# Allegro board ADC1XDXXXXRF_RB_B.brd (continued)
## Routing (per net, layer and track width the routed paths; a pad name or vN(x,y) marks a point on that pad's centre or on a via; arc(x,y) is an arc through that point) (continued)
FMC_DI-5: length 142.1
  TOP w0.102: v1(113.71,92.75) 114.2,93.25 U5.M1
  SIG2 w0.102: v1(113.71,92.75) 113.71,93.02 113.59,93.14 104.16,93.14 98.91,98.4 61.64,98.4 61.42,98.62 61.42,99.64 61.32,99.75 61.11,99.75 61.01,99.64 61.01,98.62 60.79,98.4 60.42,98.4 60.2,98.62 60.2,99.64 60.1,99.75 59.89,99.75 59.79,99.64 59.79,98.62 59.57,98.4 59.2,98.4 58.98,98.62 58.98,99.64 58.88,99.75 58.67,99.75 58.57,99.64 58.57,98.62 58.35,98.4 57.98,98.4 57.76,98.62 57.76,99.67 57.66,99.77 57.45,99.77 57.35,99.67 57.35,98.62 57.13,98.4 56.76,98.4 56.54,98.62 56.54,99.67 56.44,99.77 56.24,99.77 56.13,99.67 56.13,98.62 55.91,98.4 55.54,98.4 55.32,98.62 55.32,99.67 55.22,99.77 55.02,99.77 54.91,99.67 54.91,98.62 54.69,98.4 54.32,98.4 54.1,98.62 54.1,99.67 54,99.77 53.8,99.77 53.7,99.67 53.7,98.62 53.48,98.4 53.1,98.4 52.88,98.62 52.88,99.67 52.78,99.77 52.58,99.77 52.48,99.67 52.48,98.62 52.26,98.4 51.88,98.4 51.66,98.62 51.66,99.67 51.56,99.77 51.36,99.77 51.26,99.67 51.26,98.62 51.04,98.4 50.66,98.4 50.44,98.62 50.44,99.67 50.34,99.77 50.14,99.77 50.04,99.67 50.04,98.62 49.82,98.4 49.45,98.4 49.23,98.62 49.23,99.67 49.12,99.77 48.92,99.77 48.82,99.67 48.82,98.62 48.6,98.4 48.23,98.4 48.01,98.62 48.01,99.67 47.9,99.77 47.7,99.77 47.6,99.67 47.6,98.62 47.38,98.4 47.01,98.4 46.79,98.62 46.79,99.67 46.69,99.77 46.48,99.77 46.38,99.67 46.38,98.62 46.16,98.4 10.28,98.4 9.99,98.68 9.99,99.63 10.24,99.87 11.96,99.87 12.06,99.97 v3(12.06,100.41)
  BOTTOM w0.102: FMC.D24 v3(12.06,100.41)
FMC_DI-6: length 142.1
  TOP w0.102: U5.L6 119.2,94.24 v1(118.7,93.75)
  SIG3 w0.102: v3(80.7,92.79) 80.7,93.12 80.73,93.15 116.52,93.15 117.52,94.15 118.48,94.15 118.7,93.92 v1(118.7,93.75)
  BOTTOM w0.102: v3(80.7,92.79) 80.29,93.19 80.29,103.38 72.98,110.69 55.93,110.69 55.68,110.44 55.68,108.97 55.58,108.86 55.37,108.86 55.27,108.97 55.27,110.44 55.02,110.69 54.61,110.69 54.36,110.44 54.36,108.97 54.26,108.86 54.05,108.86 53.95,108.97 53.95,110.44 53.7,110.69 53.29,110.69 53.04,110.44 53.04,108.97 52.93,108.86 52.73,108.86 52.63,108.97 52.63,110.44 52.38,110.69 51.97,110.69 51.72,110.44 51.72,108.97 51.61,108.86 51.41,108.86 51.31,108.97 51.31,110.44 51.06,110.69 50.65,110.69 50.39,110.44 50.39,108.97 50.29,108.86 50.09,108.86 49.99,108.97 49.99,110.44 49.74,110.69 47.75,110.69 46.66,109.6 46.66,104.52 45.21,103.07 17.53,103.07 17.3,103.3 17.3,105.33 FMC.H29
FMC_DI-7: length 142.2
  TOP w0.102: v1(118.72,94.74) U5.K6
  SIG2 w0.102: v1(118.72,94.74) 118.99,94.74 119.15,94.9 119.15,95.15 118.97,95.33 118.57,95.33 118.32,95.57 118.32,96.01 117.99,96.34 104.5,96.34 97.16,103.68 93.42,103.68 93.32,103.78 93.32,104.02 93.1,104.24 92.73,104.24 92.51,104.02 92.51,103.78 92.41,103.68 92.2,103.68 92.1,103.78 92.1,104.02 91.88,104.24 91.51,104.24 91.29,104.02 91.29,103.78 91.19,103.68 90.98,103.68 90.88,103.78 90.88,104.02 90.66,104.24 90.29,104.24 90.07,104.02 90.07,103.78 89.97,103.68 89.76,103.68 89.66,103.78 89.66,104.02 89.44,104.24 89.07,104.24 88.85,104.02 88.85,103.78 88.75,103.68 88.54,103.68 88.44,103.78 88.44,104.02 88.22,104.24 87.85,104.24 87.63,104.02 87.63,103.78 87.53,103.68 87.33,103.68 87.22,103.78 87.22,104.05 87,104.27 86.63,104.27 86.41,104.05 86.41,103.78 86.31,103.68 86.11,103.68 86,103.78 86,104.05 85.78,104.27 85.41,104.27 85.19,104.05 85.19,103.78 85.09,103.68 84.89,103.68 84.79,103.78 84.79,104.05 84.56,104.27 84.19,104.27 83.97,104.05 83.97,103.78 83.87,103.68 83.67,103.68 83.57,103.78 83.57,104.05 83.35,104.27 82.97,104.27 82.75,104.05 82.75,103.78 82.65,103.68 82.45,103.68 82.35,103.78 82.35,104.05 82.13,104.27 81.75,104.27 81.53,104.05 81.53,103.78 81.43,103.68 81.23,103.68 81.13,103.78 81.13,104.05 80.91,104.27 80.54,104.27 80.31,104.05 80.31,103.78 80.21,103.68 80.01,103.68 79.91,103.78 79.91,104.05 79.69,104.27 79.32,104.27 79.1,104.05 79.1,103.78 78.99,103.68 78.79,103.68 78.69,103.78 78.69,104.05 78.47,104.27 78.1,104.27 77.88,104.05 77.88,103.78 77.77,103.68 77.57,103.68 77.47,103.78 77.47,104.05 77.25,104.27 76.88,104.27 76.66,104.05 76.66,103.78 76.56,103.68 76.35,103.68 76.25,103.78 76.25,104.05 76.03,104.27 75.66,104.27 75.44,104.05 75.44,103.78 75.34,103.68 75.13,103.68 75.03,103.78 75.03,104.05 74.81,104.27 74.44,104.27 74.22,104.05 74.22,103.78 74.12,103.68 73.91,103.68 73.81,103.78 73.81,104.05 73.59,104.27 73.22,104.27 73,104.05 73,103.78 72.9,103.68 72.69,103.68 72.59,103.78 72.59,104.05 72.37,104.27 72,104.27 71.78,104.05 71.78,103.78 71.68,103.68 71.48,103.68 71.37,103.78 71.37,104.05 71.15,104.27 70.78,104.27 70.56,104.05 70.56,103.78 70.46,103.68 70.26,103.68 70.15,103.78 70.15,104.05 69.93,104.27 69.56,104.27 69.34,104.05 69.34,103.78 69.24,103.68 69.04,103.68 68.94,103.78 68.94,104.05 68.72,104.27 68.34,104.27 68.12,104.05 68.12,103.78 68.02,103.68 67.82,103.68 67.72,103.78 67.72,104.05 67.5,104.27 67.12,104.27 66.9,104.05 66.9,103.78 66.8,103.68 66.6,103.68 66.5,103.78 66.5,104.05 66.28,104.27 65.9,104.27 65.68,104.05 65.68,103.78 65.58,103.68 65.38,103.68 65.28,103.78 65.28,104.05 65.06,104.27 64.69,104.27 64.47,104.05 64.47,103.78 64.36,103.68 64.16,103.68 64.06,103.78 64.06,104.05 63.84,104.27 63.47,104.27 63.25,104.05 63.25,103.78 63.14,103.68 62.94,103.68 62.84,103.78 62.84,104.05 62.62,104.27 62.25,104.27 62.03,104.05 62.03,103.78 61.93,103.68 61.72,103.68 61.62,103.78 61.62,104.05 61.4,104.27 61.03,104.27 60.81,104.05 60.81,103.78 60.71,103.68 60.5,103.68 60.4,103.78 60.4,104.05 60.18,104.27 59.81,104.27 59.59,104.05 59.59,103.78 59.49,103.68 59.28,103.68 59.18,103.78 59.18,104.05 58.96,104.27 58.59,104.27 58.37,104.05 58.37,103.78 58.27,103.68 58.06,103.68 57.96,103.78 57.96,104.05 57.74,104.27 57.37,104.27 57.15,104.05 57.15,103.78 57.05,103.68 56.85,103.68 56.74,103.78 56.74,104.05 56.52,104.27 56.15,104.27 55.93,104.05 55.93,103.78 55.83,103.68 55.63,103.68 55.52,103.78 55.52,104.05 55.3,104.27 54.93,104.27 54.71,104.05 54.71,103.78 54.61,103.68 54.41,103.68 54.31,103.78 54.31,104.05 54.08,104.27 53.71,104.27 53.49,104.05 53.49,103.78 53.39,103.68 53.19,103.68 53.09,103.78 53.09,104.05 52.87,104.27 52.49,104.27 52.27,104.05 52.27,103.78 52.17,103.68 51.97,103.68 51.87,103.78 51.87,104.05 51.65,104.27 51.27,104.27 51.05,104.05 51.05,103.78 50.95,103.68 50.75,103.68 50.65,103.78 50.65,104.05 50.43,104.27 50.06,104.27 49.83,104.05 49.83,103.78 49.73,103.68 49.53,103.68 49.43,103.78 49.43,104.05 49.21,104.27 48.84,104.27 48.62,104.05 48.62,103.78 48.51,103.68 48.31,103.68 48.21,103.78 48.21,104.05 47.99,104.27 47.62,104.27 47.4,104.05 47.4,103.78 47.29,103.68 47.09,103.68 46.99,103.78 46.99,104.05 46.77,104.27 46.4,104.27 46.18,104.05 46.18,103.78 46.08,103.68 15.09,103.68 15.04,103.73 15.04,104.17 15.09,104.22 v3(15.88,104.22)
  BOTTOM w0.102: FMC.G28 v3(15.88,104.22)
FMC_DI-8: length 142.1
  TOP w0.102: v1(116.72,94.74) U5.K4
  SIG2 w0.102: v1(116.72,94.74) 117.23,94.74 117.33,94.84 117.33,95.24 117.23,95.34 104.36,95.34 97.29,102.41 88.54,102.41 88.44,102.51 88.44,102.83 88.22,103.05 87.85,103.05 87.63,102.83 87.63,102.51 87.53,102.41 87.33,102.41 87.22,102.51 87.22,102.83 87,103.05 86.63,103.05 86.41,102.83 86.41,102.51 86.31,102.41 86.11,102.41 86,102.51 86,102.83 85.78,103.05 85.41,103.05 85.19,102.83 85.19,102.51 85.09,102.41 84.89,102.41 84.79,102.51 84.79,102.83 84.56,103.05 84.19,103.05 83.97,102.83 83.97,102.51 83.87,102.41 83.67,102.41 83.57,102.51 83.57,102.8 83.35,103.02 82.97,103.02 82.75,102.8 82.75,102.51 82.65,102.41 82.45,102.41 82.35,102.51 82.35,102.83 82.13,103.05 81.75,103.05 81.53,102.83 81.53,102.51 81.43,102.41 81.23,102.41 81.13,102.51 81.13,102.83 80.91,103.05 80.54,103.05 80.31,102.83 80.31,102.51 80.21,102.41 80.01,102.41 79.91,102.51 79.91,102.8 79.69,103.02 79.32,103.02 79.1,102.8 79.1,102.51 78.99,102.41 78.79,102.41 78.69,102.51 78.69,102.8 78.47,103.02 78.1,103.02 77.88,102.8 77.88,102.51 77.77,102.41 77.57,102.41 77.47,102.51 77.47,102.8 77.25,103.02 76.88,103.02 76.66,102.8 76.66,102.51 76.56,102.41 76.35,102.41 76.25,102.51 76.25,102.8 76.03,103.02 75.66,103.02 75.44,102.8 75.44,102.51 75.34,102.41 75.13,102.41 75.03,102.51 75.03,102.8 74.81,103.02 74.44,103.02 74.22,102.8 74.22,102.51 74.12,102.41 73.91,102.41 73.81,102.51 73.81,102.8 73.59,103.02 73.22,103.02 73,102.8 73,102.51 72.9,102.41 72.69,102.41 72.59,102.51 72.59,102.8 72.37,103.02 72,103.02 71.78,102.8 71.78,102.51 71.68,102.41 71.48,102.41 71.37,102.51 71.37,102.8 71.15,103.02 70.78,103.02 70.56,102.8 70.56,102.51 70.46,102.41 70.26,102.41 70.15,102.51 70.15,102.8 69.93,103.02 69.56,103.02 69.34,102.8 69.34,102.51 69.24,102.41 69.04,102.41 68.94,102.51 68.94,102.8 68.72,103.02 68.34,103.02 68.12,102.8 68.12,102.51 68.02,102.41 67.82,102.41 67.72,102.51 67.72,102.8 67.5,103.02 67.12,103.02 66.9,102.8 66.9,102.51 66.8,102.41 66.6,102.41 66.5,102.51 66.5,102.8 66.28,103.02 65.9,103.02 65.68,102.8 65.68,102.51 65.58,102.41 65.38,102.41 65.28,102.51 65.28,102.8 65.06,103.02 64.69,103.02 64.47,102.8 64.47,102.51 64.36,102.41 64.16,102.41 64.06,102.51 64.06,102.8 63.84,103.02 63.47,103.02 63.25,102.8 63.25,102.51 63.14,102.41 62.94,102.41 62.84,102.51 62.84,102.8 62.62,103.02 62.25,103.02 62.03,102.8 62.03,102.51 61.93,102.41 61.72,102.41 61.62,102.51 61.62,102.8 61.4,103.02 61.03,103.02 60.81,102.8 60.81,102.51 60.71,102.41 60.5,102.41 60.4,102.51 60.4,102.8 60.18,103.02 59.81,103.02 59.59,102.8 59.59,102.51 59.49,102.41 59.28,102.41 59.18,102.51 59.18,102.8 58.96,103.02 58.59,103.02 58.37,102.8 58.37,102.51 58.27,102.41 58.06,102.41 57.96,102.51 57.96,102.8 57.74,103.02 57.37,103.02 57.15,102.8 57.15,102.51 57.05,102.41 56.85,102.41 56.74,102.51 56.74,102.8 56.52,103.02 56.15,103.02 55.93,102.8 55.93,102.51 55.83,102.41 55.63,102.41 55.52,102.51 55.52,102.8 55.3,103.02 54.93,103.02 54.71,102.8 54.71,102.51 54.61,102.41 54.41,102.41 54.31,102.51 54.31,102.8 54.08,103.02 53.71,103.02 53.49,102.8 53.49,102.51 53.39,102.41 53.19,102.41 53.09,102.51 53.09,102.8 52.87,103.02 52.49,103.02 52.27,102.8 52.27,102.51 52.17,102.41 51.97,102.41 51.87,102.51 51.87,102.8 51.65,103.02 51.27,103.02 51.05,102.8 51.05,102.51 50.95,102.41 50.75,102.41 50.65,102.51 50.65,102.8 50.43,103.02 50.06,103.02 49.83,102.8 49.83,102.51 49.73,102.41 49.53,102.41 49.43,102.51 49.43,102.8 49.21,103.02 48.84,103.02 48.62,102.8 48.62,102.51 48.51,102.41 48.31,102.41 48.21,102.51 48.21,102.8 47.99,103.02 47.62,103.02 47.4,102.8 47.4,102.51 47.29,102.41 47.09,102.41 46.99,102.51 46.99,102.8 46.77,103.02 46.4,103.02 46.18,102.8 46.18,102.51 46.08,102.41 11.63,102.41 11.53,102.51 11.53,102.82 11.66,102.95 v3(12.06,102.95)
  BOTTOM w0.102: FMC.D27 v3(12.06,102.95)
FMC_DI-9: length 142.1
  TOP w0.102: v1(116.72,95.75) U5.J4
  SIG1 w0.102: v3(10.79,104.22) 10.79,103.78 10.9,103.68 46.07,103.68 46.17,103.78 46.17,104.05 46.39,104.27 46.76,104.27 46.98,104.05 46.98,103.78 47.09,103.68 47.29,103.68 47.39,103.78 47.39,104.05 47.61,104.27 47.98,104.27 48.2,104.05 48.2,103.78 48.3,103.68 48.51,103.68 48.61,103.78 48.61,104.05 48.83,104.27 49.2,104.27 49.42,104.05 49.42,103.78 49.52,103.68 49.73,103.68 49.83,103.78 49.83,104.05 50.05,104.27 50.42,104.27 50.64,104.05 50.64,103.78 50.74,103.68 50.95,103.68 51.05,103.78 51.05,104.05 51.27,104.27 51.64,104.27 51.86,104.05 51.86,103.78 51.96,103.68 52.17,103.68 52.27,103.78 52.27,104.05 52.49,104.27 52.86,104.27 53.08,104.05 53.08,103.78 53.18,103.68 53.38,103.68 53.49,103.78 53.49,104.05 53.71,104.27 54.08,104.27 54.3,104.05 54.3,103.78 54.4,103.68 54.6,103.68 54.71,103.78 54.71,104.05 54.93,104.27 55.3,104.27 55.52,104.05 55.52,103.78 55.62,103.68 55.82,103.68 55.92,103.78 55.92,104.05 56.15,104.27 56.52,104.27 56.74,104.05 56.74,103.78 56.84,103.68 57.04,103.68 57.14,103.78 57.14,104.05 57.36,104.27 57.74,104.27 57.96,104.05 57.96,103.78 58.06,103.68 58.26,103.68 58.36,103.78 58.36,104.05 58.58,104.27 58.96,104.27 59.18,104.05 59.18,103.78 59.28,103.68 59.48,103.68 59.58,103.78 59.58,104.05 59.8,104.27 60.17,104.27 60.4,104.05 60.4,103.78 60.5,103.68 60.7,103.68 60.8,103.78 60.8,104.05 61.02,104.27 61.39,104.27 61.61,104.05 61.61,103.78 61.72,103.68 61.92,103.68 62.02,103.78 62.02,104.05 62.24,104.27 62.61,104.27 62.83,104.05 62.83,103.78 62.94,103.68 63.14,103.68 63.24,103.78 63.24,104.05 63.46,104.27 63.83,104.27 64.05,104.05 64.05,103.78 64.15,103.68 64.36,103.68 64.46,103.78 64.46,104.05 64.68,104.27 65.05,104.27 65.27,104.05 65.27,103.78 65.37,103.68 65.58,103.68 65.68,103.78 65.68,104.05 65.9,104.27 66.27,104.27 66.49,104.05 66.49,103.78 66.59,103.68 66.8,103.68 66.9,103.78 66.9,104.05 67.12,104.27 67.49,104.27 67.71,104.05 67.71,103.78 67.81,103.68 68.02,103.68 68.12,103.78 68.12,104.05 68.34,104.27 68.71,104.27 68.93,104.05 68.93,103.78 69.03,103.68 69.23,103.68 69.34,103.78 69.34,104.05 69.56,104.27 69.93,104.27 70.15,104.05 70.15,103.78 70.25,103.68 70.45,103.68 70.56,103.78 70.56,104.05 70.78,104.27 71.15,104.27 71.37,104.05 71.37,103.78 71.47,103.68 71.67,103.68 71.77,103.78 71.77,104.05 72,104.27 72.37,104.27 72.59,104.05 72.59,103.78 72.69,103.68 72.89,103.68 72.99,103.78 72.99,104.05 73.21,104.27 73.59,104.27 73.81,104.05 73.81,103.78 73.91,103.68 74.11,103.68 74.21,103.78 74.21,104.05 74.43,104.27 74.81,104.27 75.03,104.05 75.03,103.78 75.13,103.68 75.33,103.68 75.43,103.78 75.43,104.05 75.65,104.27 76.02,104.27 76.24,104.05 76.24,103.78 76.35,103.68 76.55,103.68 76.65,103.78 76.65,104.05 76.87,104.27 77.24,104.27 77.46,104.05 77.46,103.78 77.57,103.68 77.77,103.68 77.87,103.78 77.87,104.05 78.09,104.27 78.46,104.27 78.68,104.05 78.68,103.78 78.78,103.68 78.99,103.68 79.09,103.78 79.09,104.05 79.31,104.27 79.68,104.27 79.9,104.05 79.9,103.78 80,103.68 80.21,103.68 80.31,103.78 80.31,104.05 80.53,104.27 80.9,104.27 81.12,104.05 81.12,103.78 81.22,103.68 81.43,103.68 81.53,103.78 81.53,104.05 81.75,104.27 82.12,104.27 82.34,104.05 82.34,103.78 82.44,103.68 82.65,103.68 82.75,103.78 82.75,104.02 82.97,104.24 83.34,104.24 83.56,104.02 83.56,103.78 83.66,103.68 83.86,103.68 83.97,103.78 83.97,104.02 84.19,104.24 84.56,104.24 84.78,104.02 84.78,103.78 84.88,103.68 85.08,103.68 85.19,103.78 85.19,104.02 85.41,104.24 85.78,104.24 86,104.02 86,103.78 86.1,103.68 86.3,103.68 86.4,103.78 86.4,104.02 86.63,104.24 87,104.24 87.22,104.02 87.22,103.78 87.32,103.68 87.52,103.68 87.62,103.78 87.62,104.02 87.84,104.24 88.22,104.24 88.44,104.02 88.44,103.78 88.54,103.68 98.43,103.68 108.77,93.35 115.98,93.35 117.12,94.49 117.12,95.5 116.88,95.75 v1(116.72,95.75)
  BOTTOM w0.102: FMC.C27 v3(10.79,104.22)
FMC_DI-10: length 142
  TOP w0.102: U5.K1 113.85,94.87 113.44,94.87 112.94,95.37 111.98,95.37 v1(111.61,95.75)
  SIG1 w0.102: v3(15.88,109.3) 16.41,108.76 16.82,108.76 18.09,107.49 47.26,107.49 47.37,107.59 47.37,108.97 47.59,109.19 47.96,109.19 48.18,108.97 48.18,107.59 48.28,107.49 48.48,107.49 48.58,107.59 48.58,108.97 48.8,109.19 49.18,109.19 49.4,108.97 49.4,107.59 49.5,107.49 49.7,107.49 49.8,107.59 49.8,108.97 50.02,109.19 50.4,109.19 50.62,108.97 50.62,107.59 50.72,107.49 50.92,107.49 51.02,107.59 51.02,108.97 51.24,109.19 51.62,109.19 51.84,108.97 51.84,107.59 51.94,107.49 52.14,107.49 52.24,107.59 52.24,108.97 52.46,109.19 52.83,109.19 53.05,108.97 53.05,107.59 53.16,107.49 53.36,107.49 53.46,107.59 53.46,108.97 53.68,109.19 54.05,109.19 54.27,108.97 54.27,107.59 54.38,107.49 54.58,107.49 54.68,107.59 54.68,108.97 54.9,109.19 55.27,109.19 55.49,108.97 55.49,107.59 55.59,107.49 55.8,107.49 55.9,107.59 55.9,108.97 56.12,109.19 56.49,109.19 56.71,108.97 56.71,107.59 56.81,107.49 57.02,107.49 57.12,107.59 57.12,108.97 57.34,109.19 57.71,109.19 57.93,108.97 57.93,107.59 58.03,107.49 58.24,107.49 58.34,107.59 58.34,108.97 58.56,109.19 58.93,109.19 59.15,108.97 59.15,107.59 59.25,107.49 59.46,107.49 59.56,107.59 59.56,108.97 59.78,109.19 60.15,109.19 60.37,108.97 60.37,107.59 60.47,107.49 60.67,107.49 60.78,107.59 60.78,108.97 61,109.19 61.37,109.19 61.59,108.97 61.59,107.59 61.69,107.49 97.95,107.49 110.1,95.35 111.21,95.35 v1(111.61,95.75)
  BOTTOM w0.102: FMC.H32 v3(15.88,109.3)
FMC_DI-11: length 142.1
  TOP w0.102: v1(114.72,94.74) U5.K2
  SIG3 w0.102: v1(114.72,94.74) 114.72,95.06 114.88,95.22 115.14,95.22 115.29,95.07 115.29,94.6 115.04,94.35 83.51,94.35 83.14,94.72 82.67,94.72 81.94,93.99 v3(81.94,93.95)
  BOTTOM w0.102: FMC.G31 15.24,108.53 15.04,108.33 14.83,108.33 14.73,108.43 14.73,111.51 14.94,111.71 46.94,111.71 47.19,111.96 47.19,113.18 47.3,113.28 47.5,113.28 47.6,113.18 47.6,111.96 47.85,111.71 48.26,111.71 48.51,111.96 48.51,113.18 48.62,113.28 48.82,113.28 48.92,113.18 48.92,111.96 49.17,111.71 49.59,111.71 49.84,111.96 49.84,113.18 49.94,113.28 50.14,113.28 50.24,113.18 50.24,111.96 50.49,111.71 50.91,111.71 51.16,111.96 51.16,113.16 51.26,113.26 51.46,113.26 51.56,113.16 51.56,111.96 51.81,111.71 52.23,111.71 52.48,111.96 52.48,113.16 52.58,113.26 52.78,113.26 52.88,113.16 52.88,111.96 53.13,111.71 53.55,111.71 53.8,111.96 53.8,113.16 53.9,113.26 54.1,113.26 54.2,113.16 54.2,111.96 54.45,111.71 54.87,111.71 55.12,111.96 55.12,113.16 55.22,113.26 55.42,113.26 55.53,113.16 55.53,111.96 55.78,111.71 56.19,111.71 56.44,111.96 56.44,113.16 56.54,113.26 56.74,113.26 56.85,113.16 56.85,111.96 57.1,111.71 73.84,111.71 82.14,103.4 82.14,94.16 v3(81.94,93.95)
FMC_DID+0: length 142.1
  TOP w0.102: v1(120.72,88.75) U5.T8
  SIG2 w0.102: v3(10.79,80.09) 10.79,80.49 10.92,80.62 46.16,80.62 46.38,80.84 46.38,81.15 46.48,81.25 46.69,81.25 46.79,81.15 46.79,80.84 47.01,80.62 47.38,80.62 47.6,80.84 47.6,81.15 47.7,81.25 47.9,81.25 48.01,81.15 48.01,80.84 48.23,80.62 48.6,80.62 48.82,80.84 48.82,81.15 48.92,81.25 49.12,81.25 49.23,81.15 49.23,80.84 49.45,80.62 49.82,80.62 50.04,80.84 50.04,81.15 50.14,81.25 50.34,81.25 50.44,81.15 50.44,80.84 50.66,80.62 51.04,80.62 51.26,80.84 51.26,81.15 51.36,81.25 51.56,81.25 51.66,81.15 51.66,80.84 51.88,80.62 52.26,80.62 52.48,80.84 52.48,81.15 52.58,81.25 52.78,81.25 52.88,81.15 52.88,80.84 53.1,80.62 53.48,80.62 53.7,80.84 53.7,81.15 53.8,81.25 54,81.25 54.1,81.15 54.1,80.84 54.32,80.62 54.69,80.62 54.91,80.84 54.91,81.15 55.02,81.25 55.22,81.25 55.32,81.15 55.32,80.84 55.54,80.62 55.91,80.62 56.13,80.84 56.13,81.15 56.24,81.25 56.44,81.25 56.54,81.15 56.54,80.84 56.76,80.62 57.13,80.62 57.35,80.84 57.35,81.15 57.45,81.25 57.66,81.25 57.76,81.15 57.76,80.84 57.98,80.62 58.35,80.62 58.57,80.84 58.57,81.15 58.67,81.25 58.88,81.25 58.98,81.15 58.98,80.84 59.2,80.62 59.57,80.62 59.79,80.84 59.79,81.15 59.89,81.25 60.1,81.25 60.2,81.15 60.2,80.84 60.42,80.62 60.79,80.62 61.01,80.84 61.01,81.15 61.11,81.25 61.32,81.25 61.42,81.15 61.42,80.84 61.64,80.62 62.01,80.62 62.23,80.84 62.23,81.15 62.33,81.25 62.53,81.25 62.64,81.15 62.64,80.84 62.86,80.62 63.23,80.62 63.45,80.84 63.45,81.13 63.55,81.23 63.75,81.23 63.86,81.13 63.86,80.84 64.08,80.62 64.45,80.62 64.67,80.84 64.67,81.13 64.77,81.23 64.97,81.23 65.07,81.13 65.07,80.84 65.3,80.62 65.67,80.62 65.89,80.84 65.89,81.13 65.99,81.23 66.19,81.23 66.29,81.13 66.29,80.84 66.51,80.62 66.89,80.62 67.11,80.84 67.11,81.13 67.21,81.23 67.41,81.23 67.51,81.13 67.51,80.84 67.73,80.62 68.11,80.62 68.33,80.84 68.33,81.13 68.43,81.23 68.63,81.23 68.73,81.13 68.73,80.84 68.95,80.62 69.32,80.62 69.55,80.84 69.55,81.13 69.65,81.23 69.85,81.23 69.95,81.13 69.95,80.84 70.17,80.62 70.54,80.62 70.76,80.84 70.76,81.13 70.87,81.23 71.07,81.23 71.17,81.13 71.17,80.84 71.39,80.62 71.76,80.62 71.98,80.84 71.98,81.13 72.09,81.23 72.29,81.23 72.39,81.13 72.39,80.84 72.61,80.62 72.98,80.62 73.2,80.84 73.2,81.13 73.3,81.23 73.51,81.23 73.61,81.13 73.61,80.84 73.83,80.62 74.2,80.62 74.42,80.84 74.42,81.13 74.52,81.23 74.73,81.23 74.83,81.13 74.83,80.84 75.05,80.62 75.42,80.62 75.64,80.84 75.64,81.13 75.74,81.23 75.95,81.23 76.05,81.13 76.05,80.84 76.27,80.62 76.64,80.62 76.86,80.84 76.86,81.13 76.96,81.23 77.17,81.23 77.27,81.13 77.27,80.84 77.49,80.62 77.86,80.62 78.08,80.84 78.08,81.13 78.18,81.23 78.38,81.23 78.49,81.13 78.49,80.84 78.71,80.62 92.16,80.62 95.68,84.14 120.97,84.14 121.31,84.48 121.31,88.16 v1(120.72,88.75)
  BOTTOM w0.102: FMC.D8 v3(10.79,80.09)
FMC_DID+1: length 142.1
  TOP w0.102: v1(119.72,88.75) U5.T7
  SIG2 w0.102: v3(17.14,78.82) 16.97,78.82 16.84,78.94 16.84,79.2 16.99,79.35 46.17,79.35 46.39,79.57 46.39,79.83 46.49,79.93 46.69,79.93 46.8,79.83 46.8,79.57 47.02,79.35 47.39,79.35 47.61,79.57 47.61,79.83 47.71,79.93 47.91,79.93 48.01,79.83 48.01,79.57 48.24,79.35 48.61,79.35 48.83,79.57 48.83,79.83 48.93,79.93 49.13,79.93 49.23,79.83 49.23,79.57 49.45,79.35 49.83,79.35 50.05,79.57 50.05,79.83 50.15,79.93 50.35,79.93 50.45,79.83 50.45,79.57 50.67,79.35 51.05,79.35 51.27,79.57 51.27,79.83 51.37,79.93 51.57,79.93 51.67,79.83 51.67,79.57 51.89,79.35 52.26,79.35 52.49,79.57 52.49,79.83 52.59,79.93 52.79,79.93 52.89,79.83 52.89,79.57 53.11,79.35 53.48,79.35 53.7,79.57 53.7,79.83 53.81,79.93 54.01,79.93 54.11,79.83 54.11,79.57 54.33,79.35 54.7,79.35 54.92,79.57 54.92,79.83 55.03,79.93 55.23,79.93 55.33,79.83 55.33,79.57 55.55,79.35 55.92,79.35 56.14,79.57 56.14,79.83 56.24,79.93 56.45,79.93 56.55,79.83 56.55,79.57 56.77,79.35 57.14,79.35 57.36,79.57 57.36,79.83 57.46,79.93 57.67,79.93 57.77,79.83 57.77,79.57 57.99,79.35 58.36,79.35 58.58,79.57 58.58,79.83 58.68,79.93 58.89,79.93 58.99,79.83 58.99,79.57 59.21,79.35 59.58,79.35 59.8,79.57 59.8,79.83 59.9,79.93 60.11,79.93 60.21,79.83 60.21,79.57 60.43,79.35 60.8,79.35 61.02,79.57 61.02,79.83 61.12,79.93 61.32,79.93 61.43,79.83 61.43,79.57 61.65,79.35 62.02,79.35 62.24,79.57 62.24,79.83 62.34,79.93 62.54,79.93 62.65,79.83 62.65,79.57 62.87,79.35 63.24,79.35 63.46,79.57 63.46,79.83 63.56,79.93 63.76,79.93 63.86,79.83 63.86,79.57 64.08,79.35 64.46,79.35 64.68,79.57 64.68,79.83 64.78,79.93 64.98,79.93 65.08,79.83 65.08,79.57 65.3,79.35 65.68,79.35 65.9,79.57 65.9,79.83 66,79.93 66.2,79.93 66.3,79.83 66.3,79.57 66.52,79.35 66.89,79.35 67.12,79.57 67.12,79.83 67.22,79.93 67.42,79.93 67.52,79.83 67.52,79.57 67.74,79.35 68.11,79.35 68.33,79.57 68.33,79.83 68.44,79.93 68.64,79.93 68.74,79.83 68.74,79.57 68.96,79.35 69.33,79.35 69.55,79.57 69.55,79.83 69.66,79.93 69.86,79.93 69.96,79.83 69.96,79.57 70.18,79.35 70.55,79.35 70.77,79.57 70.77,79.83 70.87,79.93 71.08,79.93 71.18,79.83 71.18,79.57 71.4,79.35 71.77,79.35 71.99,79.57 71.99,79.83 72.09,79.93 72.3,79.93 72.4,79.83 72.4,79.57 72.62,79.35 72.99,79.35 73.21,79.57 73.21,79.83 73.31,79.93 73.52,79.93 73.62,79.83 73.62,79.57 73.84,79.35 74.21,79.35 74.43,79.57 74.43,79.83 74.53,79.93 74.74,79.93 74.84,79.83 74.84,79.57 75.06,79.35 75.43,79.35 75.65,79.57 75.65,79.81 75.75,79.91 75.95,79.91 76.06,79.81 76.06,79.57 76.28,79.35 76.65,79.35 76.87,79.57 76.87,79.81 76.97,79.91 77.17,79.91 77.28,79.81 77.28,79.57 77.5,79.35 77.87,79.35 78.09,79.57 78.09,79.81 78.19,79.91 78.39,79.91 78.49,79.81 78.49,79.57 78.72,79.35 79.09,79.35 79.31,79.57 79.31,79.81 79.41,79.91 79.61,79.91 79.71,79.81 79.71,79.57 79.93,79.35 80.31,79.35 80.53,79.57 80.53,79.81 80.63,79.91 80.83,79.91 80.93,79.81 80.93,79.57 81.15,79.35 81.53,79.35 81.75,79.57 81.75,79.81 81.85,79.91 82.05,79.91 82.15,79.81 82.15,79.57 82.37,79.35 82.74,79.35 82.97,79.57 82.97,79.81 83.07,79.91 83.27,79.91 83.37,79.81 83.37,79.57 83.59,79.35 84.53,79.35 84.86,79.68 92.44,79.68 95.9,83.14 121.97,83.14 122.31,83.48 122.31,89 121.97,89.34 120.32,89.34 v1(119.72,88.75)
  BOTTOM w0.102: FMC.H7 v3(17.14,78.82)
FMC_DID+2: length 142.1
  TOP w0.102: v1(118.72,87.74) U5.U6
  SIG3 w0.102: v1(118.72,87.74) 118.31,87.74 117.7,88.34 77.36,88.34 59.68,70.66 54.38,70.66 54.16,70.44 54.16,69.75 54.05,69.65 53.85,69.65 53.75,69.75 53.75,70.44 53.53,70.66 53.16,70.66 52.94,70.44 52.94,69.75 52.84,69.65 52.63,69.65 52.53,69.75 52.53,70.44 52.31,70.66 51.94,70.66 51.72,70.44 51.72,69.75 51.62,69.65 51.41,69.65 51.31,69.75 51.31,70.44 51.09,70.66 50.72,70.66 50.5,70.44 50.5,69.72 50.4,69.62 50.19,69.62 50.09,69.72 50.09,70.44 49.87,70.66 49.5,70.66 49.28,70.44 49.28,69.72 49.18,69.62 48.97,69.62 48.87,69.72 48.87,70.44 48.65,70.66 48.28,70.66 48.06,70.44 48.06,69.72 47.96,69.62 47.76,69.62 47.65,69.72 47.65,70.44 47.43,70.66 10.44,70.66 10.26,70.84 10.26,80.56 10.32,80.62 14.07,80.62 v3(14.61,80.09)
  BOTTOM w0.102: FMC.G9 v3(14.61,80.09)
FMC_DID+3: length 142.1
  TOP w0.102: v1(116.71,86.74) U5.V4
  SIG2 w0.102: v1(116.71,86.74) 116.31,87.14 115.53,87.14 115.32,86.92 115.32,86.49 114.96,86.13 101.93,86.13 100.92,87.14 85.32,87.14 83.97,85.79 83.97,85.12 83.75,84.9 81.97,84.9 81.86,84.8 81.86,84.59 81.97,84.49 83.75,84.49 83.97,84.27 83.97,82.26 83.6,81.89 82.36,81.89 82.14,82.11 82.14,82.5 82.04,82.6 81.84,82.6 81.74,82.5 81.74,82.11 81.52,81.89 81.14,81.89 80.92,82.11 80.92,82.5 80.82,82.6 80.62,82.6 80.52,82.5 80.52,82.11 80.3,81.89 79.93,81.89 79.71,82.11 79.71,82.5 79.6,82.6 79.4,82.6 79.3,82.5 79.3,82.11 79.08,81.89 78.71,81.89 78.49,82.11 78.49,82.5 78.38,82.6 78.18,82.6 78.08,82.5 78.08,82.11 77.86,81.89 77.49,81.89 77.27,82.11 77.27,82.5 77.17,82.6 76.96,82.6 76.86,82.5 76.86,82.11 76.64,81.89 76.27,81.89 76.05,82.11 76.05,82.5 75.95,82.6 75.74,82.6 75.64,82.5 75.64,82.11 75.42,81.89 75.05,81.89 74.83,82.11 74.83,82.5 74.73,82.6 74.52,82.6 74.42,82.5 74.42,82.11 74.2,81.89 73.83,81.89 73.61,82.11 73.61,82.5 73.51,82.6 73.3,82.6 73.2,82.5 73.2,82.11 72.98,81.89 72.61,81.89 72.39,82.11 72.39,82.5 72.29,82.6 72.09,82.6 71.98,82.5 71.98,82.11 71.76,81.89 71.39,81.89 71.17,82.11 71.17,82.5 71.07,82.6 70.87,82.6 70.76,82.5 70.76,82.11 70.54,81.89 70.17,81.89 69.95,82.11 69.95,82.5 69.85,82.6 69.65,82.6 69.55,82.5 69.55,82.11 69.32,81.89 68.95,81.89 68.73,82.11 68.73,82.5 68.63,82.6 68.43,82.6 68.33,82.5 68.33,82.11 68.11,81.89 67.73,81.89 67.51,82.11 67.51,82.5 67.41,82.6 67.21,82.6 67.11,82.5 67.11,82.11 66.89,81.89 66.51,81.89 66.29,82.11 66.29,82.5 66.19,82.6 65.99,82.6 65.89,82.5 65.89,82.11 65.67,81.89 65.3,81.89 65.07,82.11 65.07,82.5 64.97,82.6 64.77,82.6 64.67,82.5 64.67,82.11 64.45,81.89 64.08,81.89 63.86,82.11 63.86,82.5 63.75,82.6 63.55,82.6 63.45,82.5 63.45,82.11 63.23,81.89 62.86,81.89 62.64,82.11 62.64,82.5 62.53,82.6 62.33,82.6 62.23,82.5 62.23,82.11 62.01,81.89 61.64,81.89 61.42,82.11 61.42,82.5 61.32,82.6 61.11,82.6 61.01,82.5 61.01,82.11 60.79,81.89 60.42,81.89 60.2,82.11 60.2,82.5 60.1,82.6 59.89,82.6 59.79,82.5 59.79,82.11 59.57,81.89 59.2,81.89 58.98,82.11 58.98,82.5 58.88,82.6 58.67,82.6 58.57,82.5 58.57,82.11 58.35,81.89 57.98,81.89 57.76,82.11 57.76,82.5 57.66,82.6 57.45,82.6 57.35,82.5 57.35,82.11 57.13,81.89 56.76,81.89 56.54,82.11 56.54,82.5 56.44,82.6 56.24,82.6 56.13,82.5 56.13,82.11 55.91,81.89 55.54,81.89 55.32,82.11 55.32,82.5 55.22,82.6 55.02,82.6 54.91,82.5 54.91,82.11 54.69,81.89 54.32,81.89 54.1,82.11 54.1,82.5 54,82.6 53.8,82.6 53.7,82.5 53.7,82.11 53.48,81.89 53.1,81.89 52.88,82.11 52.88,82.5 52.78,82.6 52.58,82.6 52.48,82.5 52.48,82.11 52.26,81.89 51.88,81.89 51.66,82.11 51.66,82.5 51.56,82.6 51.36,82.6 51.26,82.5 51.26,82.11 51.04,81.89 50.66,81.89 50.44,82.11 50.44,82.5 50.34,82.6 50.14,82.6 50.04,82.5 50.04,82.11 49.82,81.89 49.45,81.89 49.23,82.11 49.23,82.5 49.12,82.6 48.92,82.6 48.82,82.5 48.82,82.11 48.6,81.89 48.23,81.89 48.01,82.11 48.01,82.5 47.9,82.6 47.7,82.6 47.6,82.5 47.6,82.11 47.38,81.89 47.01,81.89 46.79,82.11 46.79,82.5 46.69,82.6 46.48,82.6 46.38,82.5 46.38,82.11 46.16,81.89 17.68,81.89 v3(17.14,81.36)
  BOTTOM w0.102: FMC.H10 v3(17.14,81.36)
FMC_DID+4: length 142.1
  TOP w0.102: v1(116.72,88.75) U5.T4
  SIG2 w0.102: v1(116.72,88.75) 116.3,88.75 115.7,88.14 102.84,88.14 101.84,89.14 83.72,89.14 83.5,89.36 83.5,89.43 83.4,89.53 83.2,89.53 83.1,89.43 83.1,89.36 82.88,89.14 82.5,89.14 82.28,89.36 82.28,89.43 82.18,89.53 81.98,89.53 81.88,89.43 81.88,89.36 81.66,89.14 81.28,89.14 81.06,89.36 81.06,89.43 80.96,89.53 80.76,89.53 80.66,89.43 80.66,89.36 80.44,89.14 80.06,89.14 79.84,89.36 79.84,89.43 79.74,89.53 79.54,89.53 79.44,89.43 79.44,89.36 79.22,89.14 78.46,89.14 78.13,88.82 78.13,88 77.91,87.78 76.78,87.78 76.68,87.67 76.68,87.47 76.78,87.37 77.91,87.37 78.13,87.15 78.13,86.78 77.91,86.56 76.78,86.56 76.68,86.46 76.68,86.25 76.78,86.15 77.91,86.15 78.13,85.93 78.13,84.85 77.71,84.43 75.05,84.43 74.83,84.65 74.83,85.01 74.73,85.12 74.52,85.12 74.42,85.01 74.42,84.65 74.2,84.43 73.83,84.43 73.61,84.65 73.61,85.01 73.51,85.12 73.3,85.12 73.2,85.01 73.2,84.65 72.98,84.43 72.61,84.43 72.39,84.65 72.39,85.01 72.29,85.12 72.09,85.12 71.98,85.01 71.98,84.65 71.76,84.43 71.39,84.43 71.17,84.65 71.17,85.01 71.07,85.12 70.87,85.12 70.76,85.01 70.76,84.65 70.54,84.43 70.17,84.43 69.95,84.65 69.95,85.01 69.85,85.12 69.65,85.12 69.55,85.01 69.55,84.65 69.32,84.43 68.95,84.43 68.73,84.65 68.73,85.01 68.63,85.12 68.43,85.12 68.33,85.01 68.33,84.65 68.11,84.43 67.73,84.43 67.51,84.65 67.51,85.01 67.41,85.12 67.21,85.12 67.11,85.01 67.11,84.65 66.89,84.43 66.51,84.43 66.29,84.65 66.29,85.01 66.19,85.12 65.99,85.12 65.89,85.01 65.89,84.65 65.67,84.43 65.3,84.43 65.07,84.65 65.07,85.01 64.97,85.12 64.77,85.12 64.67,85.01 64.67,84.65 64.45,84.43 64.08,84.43 63.86,84.65 63.86,85.01 63.75,85.12 63.55,85.12 63.45,85.01 63.45,84.65 63.23,84.43 62.86,84.43 62.64,84.65 62.64,85.01 62.53,85.12 62.33,85.12 62.23,85.01 62.23,84.65 62.01,84.43 61.64,84.43 61.42,84.65 61.42,85.01 61.32,85.12 61.11,85.12 61.01,85.01 61.01,84.65 60.79,84.43 60.42,84.43 60.2,84.65 60.2,85.01 60.1,85.12 59.89,85.12 59.79,85.01 59.79,84.65 59.57,84.43 59.2,84.43 58.98,84.65 58.98,85.01 58.88,85.12 58.67,85.12 58.57,85.01 58.57,84.65 58.35,84.43 57.98,84.43 57.76,84.65 57.76,85.01 57.66,85.12 57.45,85.12 57.35,85.01 57.35,84.65 57.13,84.43 56.76,84.43 56.54,84.65 56.54,85.01 56.44,85.12 56.24,85.12 56.13,85.01 56.13,84.65 55.91,84.43 55.54,84.43 55.32,84.65 55.32,85.01 55.22,85.12 55.02,85.12 54.91,85.01 54.91,84.65 54.69,84.43 54.32,84.43 54.1,84.65 54.1,85.01 54,85.12 53.8,85.12 53.7,85.01 53.7,84.65 53.48,84.43 53.1,84.43 52.88,84.65 52.88,85.01 52.78,85.12 52.58,85.12 52.48,85.01 52.48,84.65 52.26,84.43 51.88,84.43 51.66,84.65 51.66,85.01 51.56,85.12 51.36,85.12 51.26,85.01 51.26,84.65 51.04,84.43 50.66,84.43 50.44,84.65 50.44,85.01 50.34,85.12 50.14,85.12 50.04,85.01 50.04,84.65 49.82,84.43 49.45,84.43 49.23,84.65 49.23,85.01 49.12,85.12 48.92,85.12 48.82,85.01 48.82,84.65 48.6,84.43 48.23,84.43 48.01,84.65 48.01,85.01 47.9,85.12 47.7,85.12 47.6,85.01 47.6,84.65 47.38,84.43 47.01,84.43 46.79,84.65 46.79,85.01 46.69,85.12 46.48,85.12 46.38,85.01 46.38,84.65 46.16,84.43 12.29,84.43 12.06,84.2 v3(12.06,83.9)
  BOTTOM w0.102: FMC.D11 v3(12.06,83.9)
FMC_DID+5: length 142.2
  TOP w0.102: v1(115.72,87.74) U5.U3
  SIG2 w0.102: v1(115.72,87.74) 115.3,87.74 114.7,87.14 102.62,87.14 101.62,88.14 79.68,88.14 79.4,87.86 79.4,87.35 79.5,87.25 83.4,87.25 83.62,87.03 83.62,86.66 83.4,86.44 79.5,86.44 79.4,86.34 79.4,84.81 77.75,83.16 76.99,83.16 76.77,83.38 76.77,83.72 76.66,83.82 76.46,83.82 76.36,83.72 76.36,83.38 76.14,83.16 75.77,83.16 75.55,83.38 75.55,83.72 75.45,83.82 75.24,83.82 75.14,83.72 75.14,83.38 74.92,83.16 74.55,83.16 74.33,83.38 74.33,83.72 74.23,83.82 74.02,83.82 73.92,83.72 73.92,83.38 73.7,83.16 73.33,83.16 73.11,83.38 73.11,83.72 73.01,83.82 72.8,83.82 72.7,83.72 72.7,83.38 72.48,83.16 72.11,83.16 71.89,83.38 71.89,83.72 71.79,83.82 71.58,83.82 71.48,83.72 71.48,83.38 71.26,83.16 70.89,83.16 70.67,83.38 70.67,83.72 70.57,83.82 70.37,83.82 70.26,83.72 70.26,83.38 70.04,83.16 69.67,83.16 69.45,83.38 69.45,83.72 69.35,83.82 69.15,83.82 69.04,83.72 69.04,83.38 68.82,83.16 68.45,83.16 68.23,83.38 68.23,83.72 68.13,83.82 67.93,83.82 67.83,83.72 67.83,83.38 67.6,83.16 67.23,83.16 67.01,83.38 67.01,83.72 66.91,83.82 66.71,83.82 66.61,83.72 66.61,83.38 66.39,83.16 66.01,83.16 65.79,83.38 65.79,83.72 65.69,83.82 65.49,83.82 65.39,83.72 65.39,83.38 65.17,83.16 64.79,83.16 64.57,83.38 64.57,83.72 64.47,83.82 64.27,83.82 64.17,83.72 64.17,83.38 63.95,83.16 63.58,83.16 63.35,83.38 63.35,83.72 63.25,83.82 63.05,83.82 62.95,83.72 62.95,83.38 62.73,83.16 60.42,83.16 60.2,83.38 60.2,83.72 60.1,83.82 59.89,83.82 59.79,83.72 59.79,83.38 59.57,83.16 59.2,83.16 58.98,83.38 58.98,83.72 58.88,83.82 58.67,83.82 58.57,83.72 58.57,83.38 58.35,83.16 57.98,83.16 57.76,83.38 57.76,83.72 57.66,83.82 57.45,83.82 57.35,83.72 57.35,83.38 57.13,83.16 56.76,83.16 56.54,83.38 56.54,83.72 56.44,83.82 56.24,83.82 56.13,83.72 56.13,83.38 55.91,83.16 55.54,83.16 55.32,83.38 55.32,83.72 55.22,83.82 55.02,83.82 54.91,83.72 54.91,83.38 54.69,83.16 54.32,83.16 54.1,83.38 54.1,83.72 54,83.82 53.8,83.82 53.7,83.72 53.7,83.38 53.48,83.16 53.1,83.16 52.88,83.38 52.88,83.72 52.78,83.82 52.58,83.82 52.48,83.72 52.48,83.38 52.26,83.16 51.88,83.16 51.66,83.38 51.66,83.72 51.56,83.82 51.36,83.82 51.26,83.72 51.26,83.38 51.04,83.16 50.66,83.16 50.44,83.38 50.44,83.72 50.34,83.82 50.14,83.82 50.04,83.72 50.04,83.38 49.82,83.16 49.45,83.16 49.23,83.38 49.23,83.72 49.12,83.82 48.92,83.82 48.82,83.72 48.82,83.38 48.6,83.16 48.23,83.16 48.01,83.38 48.01,83.72 47.9,83.82 47.7,83.82 47.6,83.72 47.6,83.38 47.38,83.16 47.01,83.16 46.79,83.38 46.79,83.72 46.69,83.82 46.48,83.82 46.38,83.72 46.38,83.38 46.16,83.16 11,83.16 10.79,82.96 v3(10.79,82.63)
  BOTTOM w0.102: FMC.C10 v3(10.79,82.63)
FMC_DID+6: length 142.1
  TOP w0.102: v1(114.72,86.74) U5.V2
  SIG3 w0.102: v3(76.68,85.17) 76.68,86.39 77.63,87.34 114.12,87.34 v1(114.72,86.74)
  BOTTOM w0.102: FMC.H13 16.51,86.39 16.98,86.86 16.98,87.18 17.38,87.58 52.28,87.58 56.72,92.02 64.19,92.02 64.74,91.47 64.74,70.51 65.43,69.82 74.68,69.82 75.08,70.23 75.08,85.7 75.41,86.03 76.56,86.03 76.89,85.7 76.89,85.37 v3(76.68,85.17)
FMC_DID+7: length 142.1
  TOP w0.102: v1(119.71,90.75) 120.2,91.24 U5.P7
  SIG1 w0.102: v3(14.61,85.17) 15.14,85.7 15.52,85.7 15.98,86.16 15.98,87.99 15.52,88.44 9.12,88.44 8.97,88.6 8.97,94.36 9.83,95.22 11.2,95.22 11.84,95.86 46.15,95.86 46.37,96.08 46.37,96.32 46.48,96.42 46.68,96.42 46.78,96.32 46.78,96.08 47,95.86 47.37,95.86 47.59,96.08 47.59,96.32 47.7,96.42 47.9,96.42 48,96.32 48,96.08 48.22,95.86 48.59,95.86 48.81,96.08 48.81,96.32 48.91,96.42 49.12,96.42 49.22,96.32 49.22,96.08 49.44,95.86 49.81,95.86 50.03,96.08 50.03,96.32 50.13,96.42 50.34,96.42 50.44,96.32 50.44,96.08 50.66,95.86 51.03,95.86 51.25,96.08 51.25,96.32 51.35,96.42 51.56,96.42 51.66,96.32 51.66,96.08 51.88,95.86 52.25,95.86 52.47,96.08 52.47,96.32 52.57,96.42 52.78,96.42 52.88,96.32 52.88,96.08 53.1,95.86 53.47,95.86 53.69,96.08 53.69,96.32 53.79,96.42 53.99,96.42 54.1,96.32 54.1,96.08 54.32,95.86 54.69,95.86 54.91,96.08 54.91,96.32 55.01,96.42 55.21,96.42 55.32,96.32 55.32,96.08 55.54,95.86 55.91,95.86 56.13,96.08 56.13,96.32 56.23,96.42 56.43,96.42 56.53,96.32 56.53,96.08 56.76,95.86 57.13,95.86 57.35,96.08 57.35,96.32 57.45,96.42 57.65,96.42 57.75,96.32 57.75,96.08 57.97,95.86 97.43,95.86 105.16,88.14 116.99,88.14 117.32,88.47 117.32,88.95 117.51,89.14 118.97,89.14 119.31,89.48 119.31,90.35 v1(119.71,90.75)
  BOTTOM w0.102: FMC.G12 v3(14.61,85.17)
FMC_DID+8: length 142.1
  TOP w0.102: U5.R4 117.22,90.24 v1(116.72,89.75)
  SIG2 w0.102: v3(12.06,87.71) 12.6,88.24 15.47,88.24 16.15,87.55 46.16,87.55 46.38,87.77 46.38,89.28 46.48,89.38 46.69,89.38 46.79,89.28 46.79,87.77 47.01,87.55 47.38,87.55 47.6,87.77 47.6,89.28 47.7,89.38 47.9,89.38 48.01,89.28 48.01,87.77 48.23,87.55 48.6,87.55 48.82,87.77 48.82,89.28 48.92,89.38 49.12,89.38 49.23,89.28 49.23,87.77 49.45,87.55 49.82,87.55 50.04,87.77 50.04,89.28 50.14,89.38 50.34,89.38 50.44,89.28 50.44,87.77 50.66,87.55 51.04,87.55 51.26,87.77 51.26,89.28 51.36,89.38 51.56,89.38 51.66,89.28 51.66,87.77 51.88,87.55 52.26,87.55 52.48,87.77 52.48,89.28 52.58,89.38 52.78,89.38 52.88,89.28 52.88,87.77 53.1,87.55 53.48,87.55 53.7,87.77 53.7,89.28 53.8,89.38 54,89.38 54.1,89.28 54.1,87.77 54.32,87.55 54.69,87.55 54.91,87.77 54.91,89.28 55.02,89.38 55.22,89.38 55.32,89.28 55.32,87.77 55.54,87.55 55.91,87.55 56.13,87.77 56.13,89.28 56.24,89.38 56.44,89.38 56.54,89.28 56.54,87.77 56.76,87.55 57.13,87.55 57.35,87.77 57.35,89.28 57.45,89.38 57.66,89.38 57.76,89.28 57.76,87.77 57.98,87.55 72.75,87.55 76.34,91.15 102.37,91.15 103.38,90.14 114.91,90.14 115.32,89.74 115.32,89.59 115.57,89.33 115.87,89.33 116.29,89.75 v1(116.72,89.75)
  BOTTOM w0.102: FMC.D14 v3(12.06,87.71)
FMC_DID+9: length 142.1
  TOP w0.102: v1(114.72,89.75) U5.R2
  SIG2 w0.102: v3(10.79,86.44) 11.33,86.97 13.46,86.97 13.79,86.64 13.79,86.11 14.17,85.72 46.16,85.72 46.38,85.95 46.38,86.84 46.48,86.94 46.69,86.94 46.79,86.84 46.79,85.95 47.01,85.72 47.38,85.72 47.6,85.95 47.6,86.84 47.7,86.94 47.9,86.94 48.01,86.84 48.01,85.95 48.23,85.72 48.6,85.72 48.82,85.95 48.82,86.84 48.92,86.94 49.12,86.94 49.23,86.84 49.23,85.95 49.45,85.72 49.82,85.72 50.04,85.95 50.04,86.84 50.14,86.94 50.34,86.94 50.44,86.84 50.44,85.95 50.66,85.72 51.04,85.72 51.26,85.95 51.26,86.84 51.36,86.94 51.56,86.94 51.66,86.84 51.66,85.95 51.88,85.72 52.26,85.72 52.48,85.95 52.48,86.84 52.58,86.94 52.78,86.94 52.88,86.84 52.88,85.95 53.1,85.72 53.48,85.72 53.7,85.95 53.7,86.84 53.8,86.94 54,86.94 54.1,86.84 54.1,85.95 54.32,85.72 54.69,85.72 54.91,85.95 54.91,86.84 55.02,86.94 55.22,86.94 55.32,86.84 55.32,85.95 55.54,85.72 58.37,85.72 58.59,85.95 58.59,86.74 58.69,86.84 58.89,86.84 59,86.74 59,85.95 59.22,85.72 59.59,85.72 59.81,85.95 59.81,86.74 59.91,86.84 60.11,86.84 60.21,86.74 60.21,85.95 60.43,85.72 60.81,85.72 61.03,85.95 61.03,86.74 61.13,86.84 61.33,86.84 61.43,86.74 61.43,85.95 61.65,85.72 62.03,85.72 62.25,85.95 62.25,86.74 62.35,86.84 62.55,86.84 62.65,86.74 62.65,85.95 62.87,85.72 63.25,85.72 63.47,85.95 63.47,86.74 63.57,86.84 63.77,86.84 63.87,86.74 63.87,85.95 64.09,85.72 64.46,85.72 64.68,85.95 64.68,86.74 64.79,86.84 64.99,86.84 65.09,86.74 65.09,85.95 65.31,85.72 65.68,85.72 65.9,85.95 65.9,86.72 66.01,86.82 66.21,86.82 66.31,86.72 66.31,85.95 66.53,85.72 66.9,85.72 67.12,85.95 67.12,86.72 67.22,86.82 67.43,86.82 67.53,86.72 67.53,85.95 67.75,85.72 68.12,85.72 68.34,85.95 68.34,86.72 68.44,86.82 68.65,86.82 68.75,86.72 68.75,85.95 68.97,85.72 73.69,85.72 78.11,90.14 102.08,90.14 103.08,89.14 113.68,89.14 114.28,89.75 v1(114.72,89.75)
  BOTTOM w0.102: FMC.C14 v3(10.79,86.44)
FMC_DID+10: length 142.2
  TOP w0.102: v1(117.71,90.75) 118.2,91.24 U5.P5
  SIG2 w0.102: v3(17.14,90.25) 17.68,90.78 45.49,90.78 46.86,92.15 47.59,92.15 47.81,92.37 47.81,93.6 47.92,93.7 48.12,93.7 48.22,93.6 48.22,92.37 48.44,92.15 48.81,92.15 49.03,92.37 49.03,93.6 49.14,93.7 49.34,93.7 49.44,93.6 49.44,92.37 49.66,92.15 50.03,92.15 50.25,92.37 50.25,93.6 50.35,93.7 50.56,93.7 50.66,93.6 50.66,92.37 50.88,92.15 51.25,92.15 51.47,92.37 51.47,93.6 51.57,93.7 51.78,93.7 51.88,93.6 51.88,92.37 52.1,92.15 52.47,92.15 52.69,92.37 52.69,93.6 52.79,93.7 53,93.7 53.1,93.6 53.1,92.37 53.32,92.15 53.69,92.15 53.91,92.37 53.91,93.6 54.01,93.7 54.22,93.7 54.32,93.6 54.32,92.37 54.54,92.15 54.91,92.15 55.13,92.37 55.13,93.6 55.23,93.7 55.43,93.7 55.54,93.6 55.54,92.37 55.76,92.15 56.13,92.15 56.35,92.37 56.35,93.6 56.45,93.7 56.65,93.7 56.76,93.6 56.76,92.37 56.98,92.15 57.35,92.15 57.57,92.37 57.57,93.6 57.67,93.7 57.87,93.7 57.97,93.6 57.97,92.37 58.2,92.15 58.57,92.15 58.79,92.37 58.79,93.6 58.89,93.7 59.09,93.7 59.19,93.6 59.19,92.37 59.41,92.15 59.79,92.15 60.01,92.37 60.01,93.6 60.11,93.7 60.31,93.7 60.41,93.6 60.41,92.37 60.63,92.15 61.01,92.15 61.23,92.37 61.23,93.6 61.33,93.7 61.53,93.7 61.63,93.6 61.63,92.37 61.85,92.15 62.22,92.15 62.45,92.37 62.45,93.6 62.55,93.7 62.75,93.7 62.85,93.6 62.85,92.37 63.07,92.15 63.44,92.15 63.66,92.37 63.66,93.6 63.77,93.7 63.97,93.7 64.07,93.6 64.07,92.37 64.29,92.15 102.58,92.15 103.58,91.15 116.03,91.15 116.31,90.87 116.31,90.58 116.54,90.35 117.31,90.35 v1(117.71,90.75)
  BOTTOM w0.102: v3(17.14,90.25) FMC.H16
FMC_DID+11: length 142.1
  TOP w0.102: U5.P3 116.2,91.24 v1(115.7,90.75)
  SIG3 w0.102: v3(75.62,88.98) 75.62,89.31 76.45,90.14 115.1,90.14 v1(115.7,90.75)
  BOTTOM w0.102: FMC.G15 15.75,88.85 51.74,88.85 56.19,93.29 65.6,93.29 66.01,92.88 66.01,71.68 66.52,71.17 73.18,71.17 73.81,71.81 73.81,86.74 75.41,88.34 75.41,88.77 v3(75.62,88.98)
FMC_DID-0: length 142.1
  TOP w0.102: v1(119.72,87.74) U5.U7
  SIG2 w0.102: v3(10.79,81.36) 11.33,80.82 46.08,80.82 46.18,80.92 46.18,81.24 46.4,81.46 46.77,81.46 46.99,81.24 46.99,80.92 47.09,80.82 47.29,80.82 47.4,80.92 47.4,81.24 47.62,81.46 47.99,81.46 48.21,81.24 48.21,80.92 48.31,80.82 48.51,80.82 48.62,80.92 48.62,81.24 48.84,81.46 49.21,81.46 49.43,81.24 49.43,80.92 49.53,80.82 49.73,80.82 49.83,80.92 49.83,81.24 50.06,81.46 50.43,81.46 50.65,81.24 50.65,80.92 50.75,80.82 50.95,80.82 51.05,80.92 51.05,81.24 51.27,81.46 51.65,81.46 51.87,81.24 51.87,80.92 51.97,80.82 52.17,80.82 52.27,80.92 52.27,81.24 52.49,81.46 52.87,81.46 53.09,81.24 53.09,80.92 53.19,80.82 53.39,80.82 53.49,80.92 53.49,81.24 53.71,81.46 54.08,81.46 54.31,81.24 54.31,80.92 54.41,80.82 54.61,80.82 54.71,80.92 54.71,81.24 54.93,81.46 55.3,81.46 55.52,81.24 55.52,80.92 55.63,80.82 55.83,80.82 55.93,80.92 55.93,81.24 56.15,81.46 56.52,81.46 56.74,81.24 56.74,80.92 56.85,80.82 57.05,80.82 57.15,80.92 57.15,81.24 57.37,81.46 57.74,81.46 57.96,81.24 57.96,80.92 58.06,80.82 58.27,80.82 58.37,80.92 58.37,81.24 58.59,81.46 58.96,81.46 59.18,81.24 59.18,80.92 59.28,80.82 59.49,80.82 59.59,80.92 59.59,81.24 59.81,81.46 60.18,81.46 60.4,81.24 60.4,80.92 60.5,80.82 60.71,80.82 60.81,80.92 60.81,81.24 61.03,81.46 61.4,81.46 61.62,81.24 61.62,80.92 61.72,80.82 61.93,80.82 62.03,80.92 62.03,81.24 62.25,81.46 62.62,81.46 62.84,81.24 62.84,80.92 62.94,80.82 63.14,80.82 63.25,80.92 63.25,81.21 63.47,81.43 63.84,81.43 64.06,81.21 64.06,80.92 64.16,80.82 64.36,80.82 64.47,80.92 64.47,81.21 64.69,81.43 65.06,81.43 65.28,81.21 65.28,80.92 65.38,80.82 65.58,80.82 65.68,80.92 65.68,81.21 65.9,81.43 66.28,81.43 66.5,81.21 66.5,80.92 66.6,80.82 66.8,80.82 66.9,80.92 66.9,81.21 67.12,81.43 67.5,81.43 67.72,81.21 67.72,80.92 67.82,80.82 68.02,80.82 68.12,80.92 68.12,81.21 68.34,81.43 68.72,81.43 68.94,81.21 68.94,80.92 69.04,80.82 69.24,80.82 69.34,80.92 69.34,81.21 69.56,81.43 69.93,81.43 70.15,81.21 70.15,80.92 70.26,80.82 70.46,80.82 70.56,80.92 70.56,81.21 70.78,81.43 71.15,81.43 71.37,81.21 71.37,80.92 71.48,80.82 71.68,80.82 71.78,80.92 71.78,81.21 72,81.43 72.37,81.43 72.59,81.21 72.59,80.92 72.69,80.82 72.9,80.82 73,80.92 73,81.21 73.22,81.43 73.59,81.43 73.81,81.21 73.81,80.92 73.91,80.82 74.12,80.82 74.22,80.92 74.22,81.21 74.44,81.43 74.81,81.43 75.03,81.21 75.03,80.92 75.13,80.82 75.34,80.82 75.44,80.92 75.44,81.21 75.66,81.43 76.03,81.43 76.25,81.21 76.25,80.92 76.35,80.82 76.56,80.82 76.66,80.92 76.66,81.21 76.88,81.43 77.25,81.43 77.47,81.21 77.47,80.92 77.57,80.82 77.77,80.82 77.88,80.92 77.88,81.21 78.1,81.43 78.47,81.43 78.69,81.21 78.69,80.92 78.79,80.82 92.08,80.82 95.6,84.35 120.89,84.35 121.11,84.57 121.11,87.91 120.88,88.14 120.52,88.14 120.12,87.74 v1(119.72,87.74)
  BOTTOM w0.102: FMC.D9 v3(10.79,81.36)
FMC_DID-1: length 142.1
  TOP w0.102: v1(118.72,88.75) U5.T6
  SIG2 w0.102: v3(17.14,80.09) 17.68,79.55 46.08,79.55 46.19,79.65 46.19,79.92 46.41,80.14 46.78,80.14 47,79.92 47,79.65 47.1,79.55 47.3,79.55 47.41,79.65 47.41,79.92 47.63,80.14 48,80.14 48.22,79.92 48.22,79.65 48.32,79.55 48.52,79.55 48.62,79.65 48.62,79.92 48.84,80.14 49.22,80.14 49.44,79.92 49.44,79.65 49.54,79.55 49.74,79.55 49.84,79.65 49.84,79.92 50.06,80.14 50.44,80.14 50.66,79.92 50.66,79.65 50.76,79.55 50.96,79.55 51.06,79.65 51.06,79.92 51.28,80.14 51.65,80.14 51.88,79.92 51.88,79.65 51.98,79.55 52.18,79.55 52.28,79.65 52.28,79.92 52.5,80.14 52.87,80.14 53.09,79.92 53.09,79.65 53.2,79.55 53.4,79.55 53.5,79.65 53.5,79.92 53.72,80.14 54.09,80.14 54.31,79.92 54.31,79.65 54.42,79.55 54.62,79.55 54.72,79.65 54.72,79.92 54.94,80.14 55.31,80.14 55.53,79.92 55.53,79.65 55.63,79.55 55.84,79.55 55.94,79.65 55.94,79.92 56.16,80.14 56.53,80.14 56.75,79.92 56.75,79.65 56.85,79.55 57.06,79.55 57.16,79.65 57.16,79.92 57.38,80.14 57.75,80.14 57.97,79.92 57.97,79.65 58.07,79.55 58.28,79.55 58.38,79.65 58.38,79.92 58.6,80.14 58.97,80.14 59.19,79.92 59.19,79.65 59.29,79.55 59.5,79.55 59.6,79.65 59.6,79.92 59.82,80.14 60.19,80.14 60.41,79.92 60.41,79.65 60.51,79.55 60.71,79.55 60.82,79.65 60.82,79.92 61.04,80.14 61.41,80.14 61.63,79.92 61.63,79.65 61.73,79.55 61.93,79.55 62.04,79.65 62.04,79.92 62.26,80.14 62.63,80.14 62.85,79.92 62.85,79.65 62.95,79.55 63.15,79.55 63.25,79.65 63.25,79.92 63.48,80.14 63.85,80.14 64.07,79.92 64.07,79.65 64.17,79.55 64.37,79.55 64.47,79.65 64.47,79.92 64.69,80.14 65.07,80.14 65.29,79.92 65.29,79.65 65.39,79.55 65.59,79.55 65.69,79.65 65.69,79.92 65.91,80.14 66.29,80.14 66.51,79.92 66.51,79.65 66.61,79.55 66.81,79.55 66.91,79.65 66.91,79.92 67.13,80.14 67.5,80.14 67.73,79.92 67.73,79.65 67.83,79.55 68.03,79.55 68.13,79.65 68.13,79.92 68.35,80.14 68.72,80.14 68.94,79.92 68.94,79.65 69.05,79.55 69.25,79.55 69.35,79.65 69.35,79.92 69.57,80.14 69.94,80.14 70.16,79.92 70.16,79.65 70.27,79.55 70.47,79.55 70.57,79.65 70.57,79.92 70.79,80.14 71.16,80.14 71.38,79.92 71.38,79.65 71.48,79.55 71.69,79.55 71.79,79.65 71.79,79.92 72.01,80.14 72.38,80.14 72.6,79.92 72.6,79.65 72.7,79.55 72.91,79.55 73.01,79.65 73.01,79.92 73.23,80.14 73.6,80.14 73.82,79.92 73.82,79.65 73.92,79.55 74.13,79.55 74.23,79.65 74.23,79.92 74.45,80.14 74.82,80.14 75.04,79.92 75.04,79.65 75.14,79.55 75.35,79.55 75.45,79.65 75.45,79.89 75.67,80.11 76.04,80.11 76.26,79.89 76.26,79.65 76.36,79.55 76.56,79.55 76.67,79.65 76.67,79.89 76.89,80.11 77.26,80.11 77.48,79.89 77.48,79.65 77.58,79.55 77.78,79.55 77.89,79.65 77.89,79.89 78.11,80.11 78.48,80.11 78.7,79.89 78.7,79.65 78.8,79.55 79,79.55 79.1,79.65 79.1,79.89 79.32,80.11 79.7,80.11 79.92,79.89 79.92,79.65 80.02,79.55 80.22,79.55 80.32,79.65 80.32,79.89 80.54,80.11 80.92,80.11 81.14,79.89 81.14,79.65 81.24,79.55 81.44,79.55 81.54,79.65 81.54,79.89 81.76,80.11 82.13,80.11 82.36,79.89 82.36,79.65 82.46,79.55 82.66,79.55 82.76,79.65 82.76,79.89 82.98,80.11 83.35,80.11 83.57,79.89 83.57,79.65 83.68,79.55 84.45,79.55 84.78,79.88 92.35,79.88 95.81,83.34 121.88,83.34 122.11,83.57 122.11,88.92 121.88,89.14 120.46,89.14 120.14,88.82 120.14,88.52 119.96,88.34 119.12,88.34 v1(118.72,88.75)
  BOTTOM w0.102: FMC.H8 v3(17.14,80.09)
FMC_DID-2: length 142.1
  TOP w0.102: v1(117.72,87.74) U5.U5
  SIG3 w0.102: v3(14.61,81.36) 14.61,80.98 14.45,80.82 10.24,80.82 10.06,80.64 10.06,70.76 10.36,70.46 47.35,70.46 47.45,70.36 47.45,69.64 47.67,69.42 48.04,69.42 48.26,69.64 48.26,70.36 48.36,70.46 48.57,70.46 48.67,70.36 48.67,69.64 48.89,69.42 49.26,69.42 49.48,69.64 49.48,70.36 49.58,70.46 49.79,70.46 49.89,70.36 49.89,69.64 50.11,69.42 50.48,69.42 50.7,69.64 50.7,70.36 50.8,70.46 51.01,70.46 51.11,70.36 51.11,69.66 51.33,69.44 51.7,69.44 51.92,69.66 51.92,70.36 52.02,70.46 52.23,70.46 52.33,70.36 52.33,69.66 52.55,69.44 52.92,69.44 53.14,69.66 53.14,70.36 53.24,70.46 53.44,70.46 53.55,70.36 53.55,69.66 53.77,69.44 54.14,69.44 54.36,69.66 54.36,70.36 54.46,70.46 59.77,70.46 77.44,88.14 117.62,88.14 117.72,88.04 v1(117.72,87.74)
  BOTTOM w0.102: FMC.G10 v3(14.61,81.36)
FMC_DID-3: length 142.1
  TOP w0.102: v1(116.72,87.74) U5.U4
  SIG2 w0.102: v1(116.72,87.74) 116.32,87.34 115.45,87.34 115.12,87.01 115.12,86.57 114.88,86.33 102.01,86.33 101.01,87.34 85.23,87.34 83.77,85.88 83.77,85.2 83.67,85.1 81.88,85.1 81.66,84.88 81.66,84.51 81.88,84.29 83.67,84.29 83.77,84.19 83.77,82.35 83.52,82.09 82.45,82.09 82.35,82.19 82.35,82.58 82.13,82.8 81.75,82.8 81.53,82.58 81.53,82.19 81.43,82.09 81.23,82.09 81.13,82.19 81.13,82.58 80.91,82.8 80.54,82.8 80.31,82.58 80.31,82.19 80.21,82.09 80.01,82.09 79.91,82.19 79.91,82.58 79.69,82.8 79.32,82.8 79.1,82.58 79.1,82.19 78.99,82.09 78.79,82.09 78.69,82.19 78.69,82.58 78.47,82.8 78.1,82.8 77.88,82.58 77.88,82.19 77.77,82.09 77.57,82.09 77.47,82.19 77.47,82.58 77.25,82.8 76.88,82.8 76.66,82.58 76.66,82.19 76.56,82.09 76.35,82.09 76.25,82.19 76.25,82.58 76.03,82.8 75.66,82.8 75.44,82.58 75.44,82.19 75.34,82.09 75.13,82.09 75.03,82.19 75.03,82.58 74.81,82.8 74.44,82.8 74.22,82.58 74.22,82.19 74.12,82.09 73.91,82.09 73.81,82.19 73.81,82.58 73.59,82.8 73.22,82.8 73,82.58 73,82.19 72.9,82.09 72.69,82.09 72.59,82.19 72.59,82.58 72.37,82.8 72,82.8 71.78,82.58 71.78,82.19 71.68,82.09 71.48,82.09 71.37,82.19 71.37,82.58 71.15,82.8 70.78,82.8 70.56,82.58 70.56,82.19 70.46,82.09 70.26,82.09 70.15,82.19 70.15,82.58 69.93,82.8 69.56,82.8 69.34,82.58 69.34,82.19 69.24,82.09 69.04,82.09 68.94,82.19 68.94,82.58 68.72,82.8 68.34,82.8 68.12,82.58 68.12,82.19 68.02,82.09 67.82,82.09 67.72,82.19 67.72,82.58 67.5,82.8 67.12,82.8 66.9,82.58 66.9,82.19 66.8,82.09 66.6,82.09 66.5,82.19 66.5,82.58 66.28,82.8 65.9,82.8 65.68,82.58 65.68,82.19 65.58,82.09 65.38,82.09 65.28,82.19 65.28,82.58 65.06,82.8 64.69,82.8 64.47,82.58 64.47,82.19 64.36,82.09 64.16,82.09 64.06,82.19 64.06,82.58 63.84,82.8 63.47,82.8 63.25,82.58 63.25,82.19 63.14,82.09 62.94,82.09 62.84,82.19 62.84,82.58 62.62,82.8 62.25,82.8 62.03,82.58 62.03,82.19 61.93,82.09 61.72,82.09 61.62,82.19 61.62,82.58 61.4,82.8 61.03,82.8 60.81,82.58 60.81,82.19 60.71,82.09 60.5,82.09 60.4,82.19 60.4,82.58 60.18,82.8 59.81,82.8 59.59,82.58 59.59,82.19 59.49,82.09 59.28,82.09 59.18,82.19 59.18,82.58 58.96,82.8 58.59,82.8 58.37,82.58 58.37,82.19 58.27,82.09 58.06,82.09 57.96,82.19 57.96,82.58 57.74,82.8 57.37,82.8 57.15,82.58 57.15,82.19 57.05,82.09 56.85,82.09 56.74,82.19 56.74,82.58 56.52,82.8 56.15,82.8 55.93,82.58 55.93,82.19 55.83,82.09 55.63,82.09 55.52,82.19 55.52,82.58 55.3,82.8 54.93,82.8 54.71,82.58 54.71,82.19 54.61,82.09 54.41,82.09 54.31,82.19 54.31,82.58 54.08,82.8 53.71,82.8 53.49,82.58 53.49,82.19 53.39,82.09 53.19,82.09 53.09,82.19 53.09,82.58 52.87,82.8 52.49,82.8 52.27,82.58 52.27,82.19 52.17,82.09 51.97,82.09 51.87,82.19 51.87,82.58 51.65,82.8 51.27,82.8 51.05,82.58 51.05,82.19 50.95,82.09 50.75,82.09 50.65,82.19 50.65,82.58 50.43,82.8 50.06,82.8 49.83,82.58 49.83,82.19 49.73,82.09 49.53,82.09 49.43,82.19 49.43,82.58 49.21,82.8 48.84,82.8 48.62,82.58 48.62,82.19 48.51,82.09 48.31,82.09 48.21,82.19 48.21,82.58 47.99,82.8 47.62,82.8 47.4,82.58 47.4,82.19 47.29,82.09 47.09,82.09 46.99,82.19 46.99,82.58 46.77,82.8 46.4,82.8 46.18,82.58 46.18,82.19 46.08,82.09 17.68,82.09 v3(17.14,82.63)
  BOTTOM w0.102: FMC.H11 v3(17.14,82.63)
